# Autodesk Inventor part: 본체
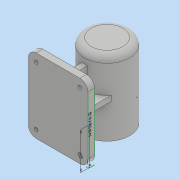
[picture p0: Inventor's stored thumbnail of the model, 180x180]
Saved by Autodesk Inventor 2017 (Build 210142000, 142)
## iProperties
Part Number: 본체
Material: 일반
Document SubType Name: Modeling
Designer: mrc
Density: 1 g/cm^3
Appearance: 기본값
Author: mrc
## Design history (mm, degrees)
sketch "스케치2"
  geometry: L1 (0, 56)-(0, -56); L2 (34, 46)-(34, -56); L3 (34, -56)-(21, -56); L4 (21, -56)-(21, -41); L5 (21, -41)-(24, -41); L6 (24, -41)-(24, 13); L7 (24, 13)-(21, 13); L8 (21, 13)-(21, 25); L9 (21, 25)-(17.5, 25); L10 (17.5, 25)-(17.5, 43); L11 (17.5, 43)-(16, 43); L12 (16, 43)-(16, 47); L13 (16, 47)-(10.5, 47); L14 (10.5, 47)-(10.5, 50); L15 (10.5, 50)-(0, 50); L16 (24, 56)-(0, 56); A1 r 10 centre (24, 46) between (34, 46) and (24, 56); 2 further points
  constraints: 32 end point, 7 perpendicular, 4 vertical, 3 horizontal, 2 point on circle, 2 tangent, 1 centre point, 1 coincident, 1 horizontal alignment, 1 midpoint, 1 parallel, 1 point on line
  dimensions: "d3" = 68 diameter of L2 L1; "d5" = 42 diameter of L4 L1; "d6" = 48 diameter of L6 L1; "d7" = 42 diameter of L8 L1; "d9" = 15 distance between parallel lines of L3 L5; "d10" = 54 distance from line of L4.end L7; "d11" = 112 distance of L1.start L1.end; "d12" = 12 distance of L7.end L8.end; "d13" = 18 distance of L9.end L10.end; "d14" = 35 diameter of L10 L1; "d15" = 32 diameter of L12 L1; "d17" = 4 distance between parallel lines of L11 L13; "d18" = 3 distance of L13.end L14.end; "d19" = 21 diameter of L14 L1; "d20" = 10 radius of A1
revolve "회전1" sketch "스케치2" stored, may be unused: angle "d21" = 90 deg
sketch "스케치3"
  geometry: L1 (45, -64)-(-45, -64); L2 (-45, -64)-(-45, -74); L3 (-45, -74)-(45, -74); L4 (45, -74)-(45, -64); 2 further points
  constraints: 8 end point, 2 parallel, 1 horizontal, 1 midpoint, 1 perpendicular, 1 vertical alignment
  dimensions: "d22" = 10 distance of L1.end L2.end; "d23" = 74 distance from line of L3 point (0, 0); "d24" = 90 distance of L2.end L3.end
extrude "돌출2" join sketch "스케치3" stored distance "d25" = 112; taper "d26" = 0 deg
sketch "스케치4"
  geometry: L1 (72, 60)-(18, 60); L2 (18, 60)-(18, 52); L3 (18, 52)-(72, 52); L4 (72, 52)-(72, 60); L5 (72, 60)-(18, 52); L6 (18, 60)-(72, 52); L7 (49, 94)-(41, 94); L8 (41, 94)-(41, 18); L9 (41, 18)-(49, 18); L10 (49, 18)-(49, 94); L11 (49, 94)-(41, 18); L12 (41, 94)-(49, 18); L13 (0, 112)-(0, 0) reference; L14 (0, 0)-(90, 0) reference; 1 further point
  constraints: 24 end point, 4 midpoint, 4 parallel, 2 horizontal, 2 perpendicular
  dimensions: "d27" = 8 distance of L8.end L9.end; "d28" = 8 distance of L1.end L2.end; "d29" = 18 distance between parallel lines of L13 L2; "d30" = 18 distance between parallel lines of L14 L9
extrude "돌출3" join sketch "스케치4" stored distance "d31" = 10; taper "d32" = 0 deg
sketch "스케치5"
  geometry: 2 further points
  constraints: 1 vertical alignment
  dimensions: "d33" = 26 distance of point (0, 0) point (0, 26)
hole "구멍1" sketch "스케치5" at (0, 26) diameter "d34" = 3.242; stored, may be unused: countersink angle "d38" = 90 deg, drill point angle "d40" = 118 deg; dims "d35" = 8, "d36" = 4, "d37" = 2, "d39" = 11
fillet "모깎기1" dims "d44" = 12
hole "구멍2" diameter "d47" = 5.5; stored, may be unused: countersink angle "d51" = 90 deg, drill point angle "d53" = 0 deg; dims "d45" = 10, "d46" = 10, "d48" = 8, "d49" = 9.5, "d50" = 5.4, "d52" = 11
hole "구멍3" diameter "d56" = 5.5; stored, may be unused: countersink angle "d60" = 90 deg, drill point angle "d62" = 0 deg; dims "d54" = 10, "d55" = 10, "d57" = 8, "d58" = 9.5, "d59" = 5.4, "d61" = 11
hole "구멍4" diameter "d65" = 5.5; stored, may be unused: countersink angle "d69" = 90 deg, drill point angle "d71" = 0 deg; dims "d63" = 10, "d64" = 10, "d66" = 8, "d67" = 9.5, "d68" = 5.4, "d70" = 11
hole "구멍5" diameter "d74" = 5.5; stored, may be unused: countersink angle "d78" = 90 deg, drill point angle "d80" = 0 deg; dims "d72" = 10, "d73" = 10, "d75" = 8, "d76" = 9.5, "d77" = 5.4, "d79" = 11
sketch "스케치6"
  geometry: L1 (0, 10)-(88, 10) reference; L2 (100, 0)-(100, 10) reference; L3 (88, 0)-(0, 0) reference; 2 further points
  constraints: 1 other
  dimensions: "d82" = 56 distance from line of L2 point (44, 3); "d83" = 3 distance from line of L3 point (44, 3)
node "솔리드2"
pattern_circular "원형 패턴1" dims angle "d42" = 360 deg
